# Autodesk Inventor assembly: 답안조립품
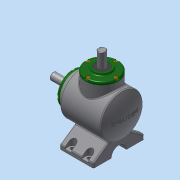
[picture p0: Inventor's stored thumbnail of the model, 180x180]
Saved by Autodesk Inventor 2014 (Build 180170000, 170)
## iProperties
Created: 2017-04
Part Number: 답안조립품
Document SubType Name: Assembly
Designer: SCD-A15
Author: SCD-A15
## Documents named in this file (14)
- C:\Users\SCD-A15\Desktop\470408V1013\답안조립품.iam
- C:\Users\SCD-A15\Desktop\470408V1013\본체.ipt
- C:\Users\SCD-A15\Desktop\470408V1013\메인 베벨기어.ipt
- C:\Users\SCD-A15\Desktop\470408V1013\메인 축.ipt
- 메인 축.ipt
- C:\Users\SCD-A15\Desktop\470408V1013\베어링 6203.ipt
- C:\Users\SCD-A15\Desktop\470408V1013\볼트 M4.ipt
- C:\Users\SCD-A15\Desktop\470408V1013\서브 베벨기어.ipt
- C:\Users\SCD-A15\Desktop\470408V1013\서브 축.ipt
- 서브 축.ipt
- C:\Users\SCD-A15\Desktop\470408V1013\오일실 17 32 8.ipt
- C:\Users\SCD-A15\Desktop\470408V1013\커버.ipt
- C:\Users\SCD-A15\Desktop\470408V1013\키 4x4.ipt
- C:\Users\SCD-A15\Desktop\470408V1013\키 5x5.ipt
